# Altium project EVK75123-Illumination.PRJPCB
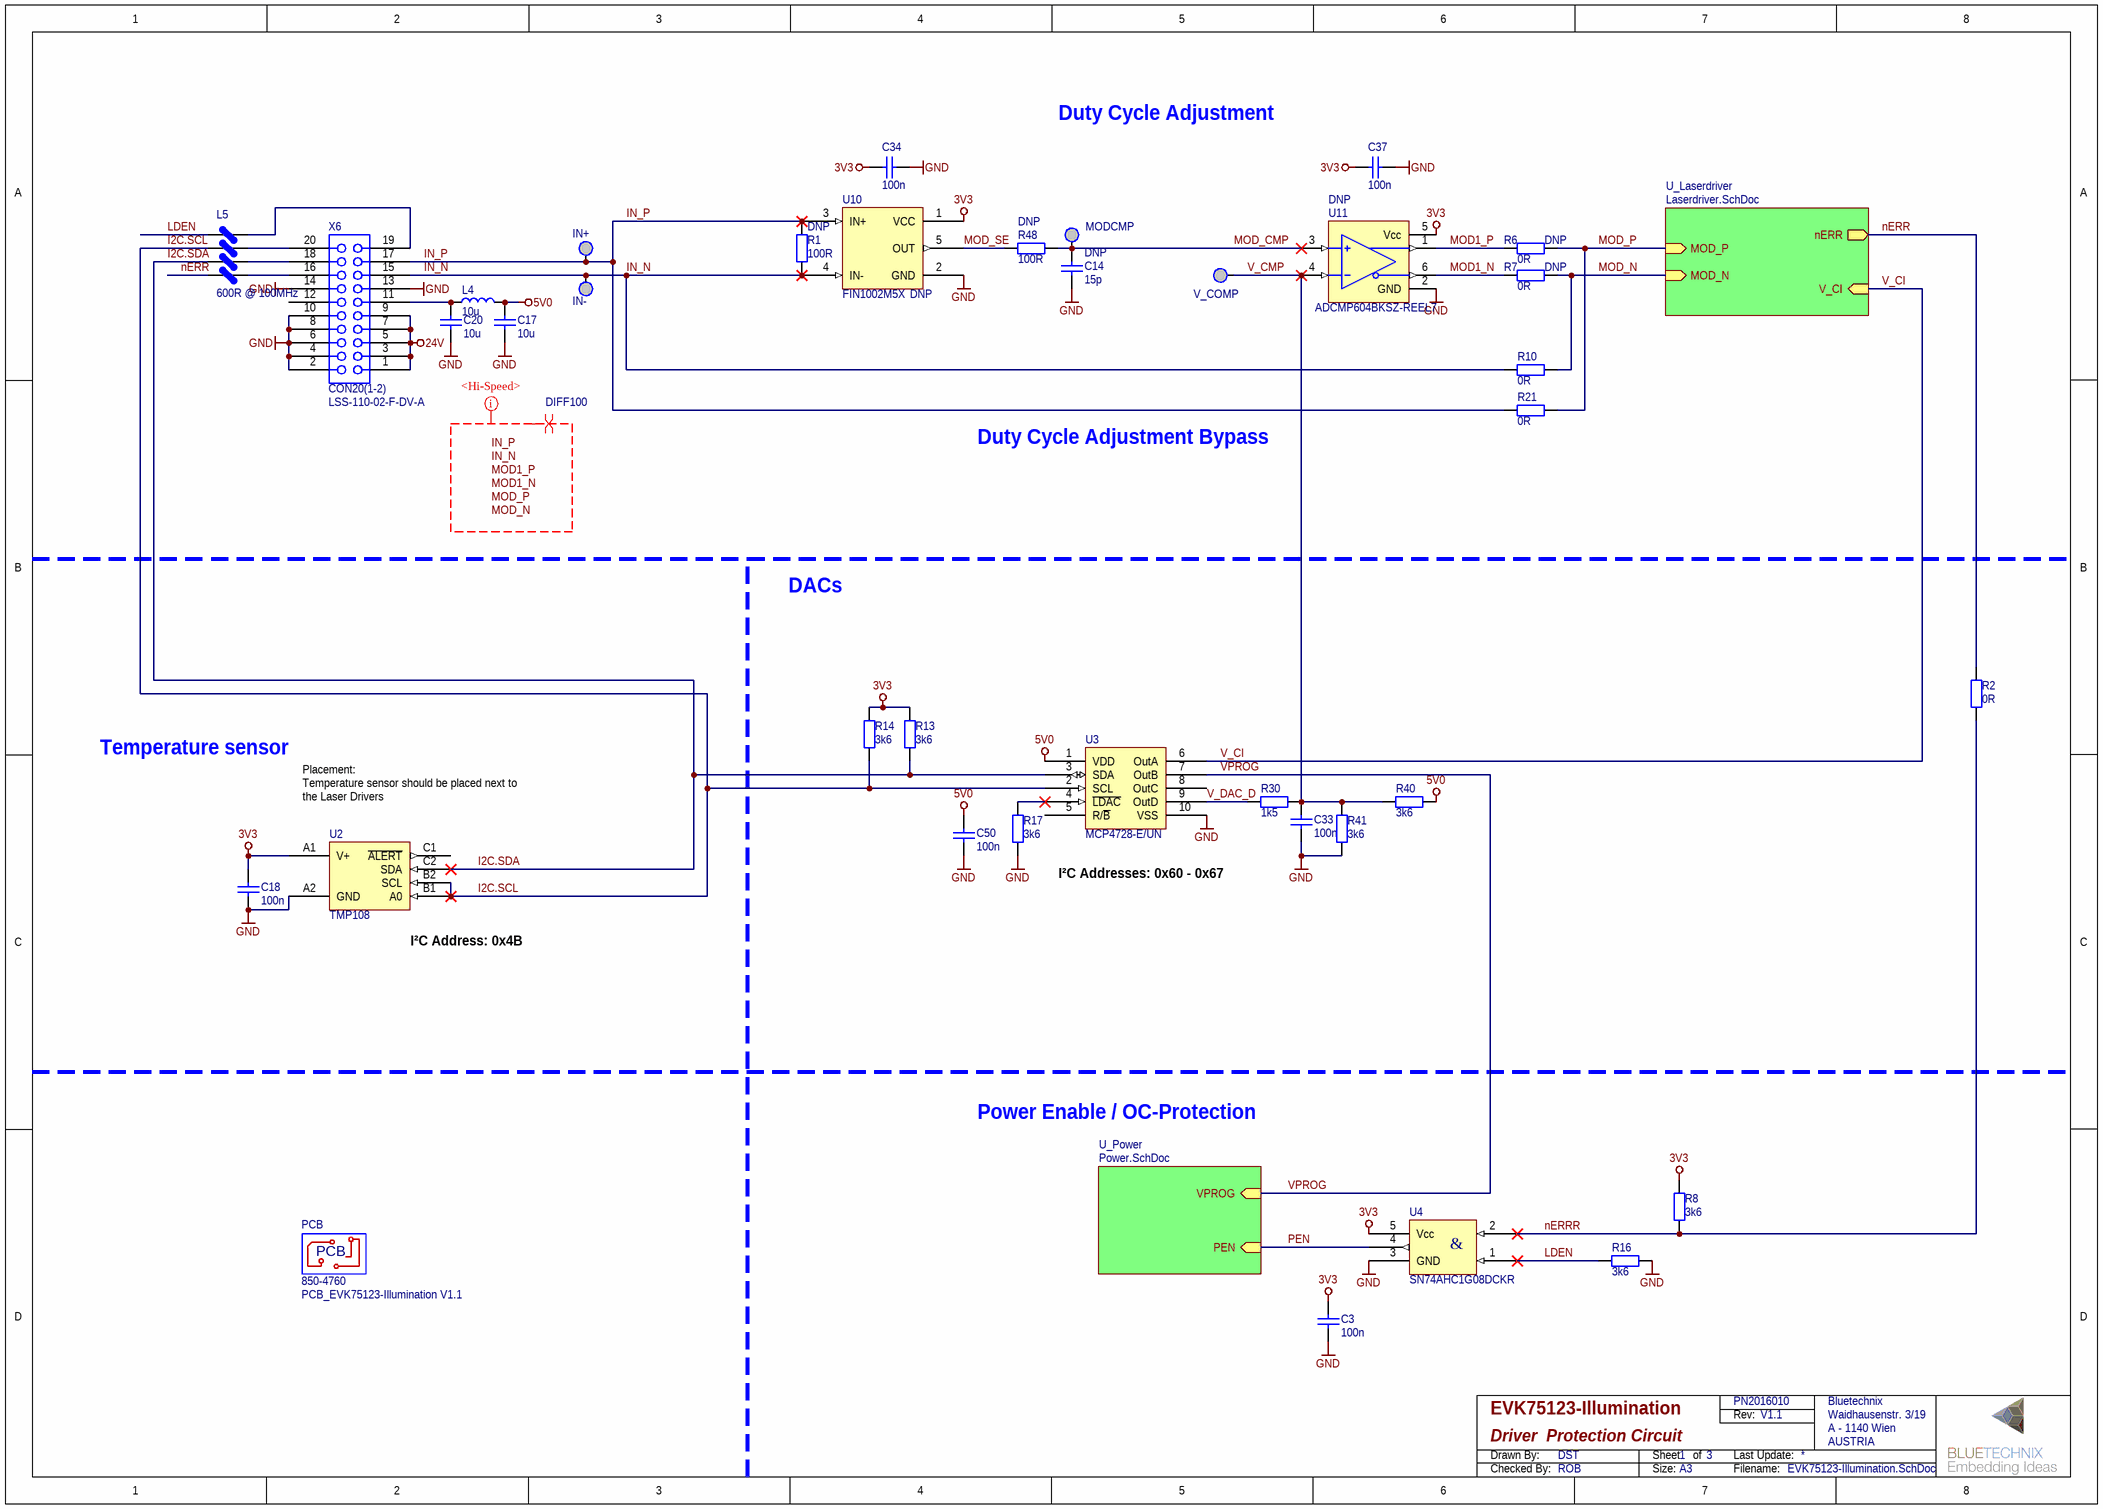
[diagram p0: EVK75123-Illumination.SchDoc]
prj_name: EVK75123-Illumination; prj_num: PN2016010; prj_vers: V1.1
3 sheets, 91 parts. Net scope: hierarchical (ports join the sheet entries above them; power ports are global).
Board file: EVK75123-Illumination.PcbDoc
Sheets:
  EVK75123-Illumination.SchDoc
    U_Power = Power.SchDoc
    U_Laserdriver = Laserdriver.SchDoc

## Sheet EVK75123-Illumination.SchDoc: Driver  Protection Circuit
size A3; CheckedBy: ROB; Author: Vorname Nachname; DrawnBy: DST; Organization: Bluetechnix; Address1: Waidhausenstr. 3/19; Address2: A - 1140 Wien; Address3: AUSTRIA; DocumentNumber: 1; Revision: V1.0; SheetNumber: 1; SheetTotal: 3

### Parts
C3  C: 100n  [0402]  (hidden comment: Capacitor non-polarized)
C14  C: 15p  MountOption: DNP  [0402]  (hidden comment: Capacitor non-polarized)
C17  C: 10u  [0805]  (hidden comment: Capacitor non-polarized)
C18  C: 100n  [0402]  (hidden comment: Capacitor non-polarized)
C20  C: 10u  [0805]  (hidden comment: Capacitor non-polarized)
C33  C: 100n  [0402]  (hidden comment: Capacitor non-polarized)
C34  C: 100n  [0402]  (hidden comment: Capacitor non-polarized)
C37  C: 100n  [0402]  (hidden comment: Capacitor non-polarized)
C50  C: 100n  [0402]  (hidden comment: Capacitor non-polarized)
IN+  Test Pad  [PAD_1mm_SMD]  (value not drawn)  (no BOM)
IN-  Test Pad  [PAD_1mm_SMD]  (value not drawn)  (no BOM)
L4  L: 10u  [1210]  (hidden comment: Inductor)
L5  Z: 600R @ 100MHz  [1206_FB-array]  (hidden comment: Ferrite)
MODCMP  Test Pad  [PAD_1mm_SMD]  (value not drawn)  (no BOM)
PCB  850-4760  [PCB]
R1  R: 100R  MountOption: DNP  [0402]  (hidden comment: Resistor)
R2  R: 0R  [0805]  (hidden comment: Resistor)
R6  R: 0R  MountOption: DNP  [0805]  (hidden comment: Resistor)
R7  R: 0R  MountOption: DNP  [0805]  (hidden comment: Resistor)
R8  R: 3k6  [0402]  (hidden comment: Resistor)
R10  R: 0R  [0805]  (hidden comment: Resistor)
R13  R: 3k6  [0402]  (hidden comment: Resistor)
R14  R: 3k6  [0402]  (hidden comment: Resistor)
R16  R: 3k6  [0402]  (hidden comment: Resistor)
R17  R: 3k6  [0402]  (hidden comment: Resistor)
R21  R: 0R  [0805]  (hidden comment: Resistor)
R30  R: 1k5  [0402]  (hidden comment: Resistor)
R40  R: 3k6  [0402]  (hidden comment: Resistor)
R41  R: 3k6  [0402]  (hidden comment: Resistor)
R48  R: 100R  MountOption: DNP  [0402]  (hidden comment: Resistor)
U2  TMP108  [BGA6-0.4-0.25-1.2x0.8]
U3  NAME: MCP4728-E/UN  [MSOP10-0.5-5]  (hidden comment: MCP4728)
U4  NAME: SN74AHC1G08DCKR  [SOT353-0.65--2.6]  (hidden comment: Single-Gate Dual-Input AND-Logic-Gate)
U10  NAME: FIN1002M5X  MountOption: DNP  [SOT23-5-0.95--3.6]  (hidden comment: FIN1002)
U11  NAME: ADCMP604BKSZ-REEL7  MountOption: DNP  [SOT363-0.65--2.6]  (hidden comment: ADCMP604)
V_COMP  Test Pad  [PAD_1mm_SMD]  (value not drawn)  (no BOM)
X6  CON20(1-2)  NAME: LSS-110-02-F-DV-A  [SAM-LSS-110-02-F-DV-A]

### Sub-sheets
U_Laserdriver = Laserdriver.SchDoc: MOD_P (in), MOD_N (in), nERR (out), V_CI (in)
U_Power = Power.SchDoc: PEN (in), VPROG (in)

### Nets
3V3: C3.1 C18.2 C34.1 C37.1 R8.2 R13.2 R14.2 U2.A1(V+) U4.5(Vcc) U10.1(VCC) U11.5(Vcc)
5V0: C17.2 C50.2 L4.2 R40.1 U3.1(VDD)
24V: X6.1 X6.3 X6.5 X6.7 X6.9
GND: C3.2 C14.1 C17.1 C18.1 C20.1 C33.2 C34.2 C37.2 C50.1 R16.2 R17.1 R41.2 U2.A2(GND) U3.10(VSS) U4.3(GND) U10.2(GND) U11.2(GND) X6.2 X6.4 X6.6 X6.8 X6.10 X6.13 X6.14
I2C.SCL: L5.3 R14.1 U2.B1(A0) U2.B2(SCL) U3.2(SCL)
I2C.SDA: L5.2 R13.1 U2.C2(SDA) U3.3(SDA)
IN_N: IN-.1 R1.2 R10.2 U10.4(IN-) X6.15
IN_P: IN+.1 R1.1 R21.2 U10.3(IN+) X6.17
LDEN: L5.4 R16.1 U4.1(inB)
MOD1_N: R7.2 U11.6(~{Q})
MOD1_P: R6.2 U11.1(Q)
MOD_CMP: C14.2 MODCMP.1 R48.2 U11.3(VP)
MOD_N: R7.1 R10.1 ; sheet U_Laserdriver/MOD_N
MOD_P: R6.1 R21.1 ; sheet U_Laserdriver/MOD_P
MOD_SE: R48.1 U10.5(OUT)
nERR: L5.1 R2.1 ; sheet U_Laserdriver/nERR
nERRR: R2.2 R8.1 U4.2(inA)
PEN: U4.4(out) ; sheet U_Power/PEN
V_CI: U3.6(OutA) ; sheet U_Laserdriver/V_CI
V_CMP: C33.1 R30.2 R40.2 R41.1 U11.4(VN) V_COMP.1
V_DAC_D: R30.1 U3.9(OutD)
VPROG: U3.7(OutB) ; sheet U_Power/VPROG
NetC20_2: C20.2 L4.1 X6.11
NetL5_5: L5.5 X6.19
NetL5_6: L5.6 X6.20
NetL5_7: L5.7 X6.18
NetL5_8: L5.8 X6.16
NetR17_2: R17.2 U3.4(~{LDAC})

Not connected (* = marked no-connect by the designer): U2 C1(~{ALERT}); U3 5(R/~{B}) 8(OutC); X6 12

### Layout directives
net class <Hi-Speed>: IN_N, IN_P, MOD1_N, MOD1_P, MOD_N, MOD_P
differential pair; net class DIFF100: IN_N, IN_P, MOD1_N, MOD1_P, MOD_N, MOD_P

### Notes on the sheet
- Duty Cycle Adjustment
- Duty Cycle Adjustment Bypass
- DACs
- Temperature sensor
- Placement:
  Temperature sensor should be placed next to the Laser Drivers
- I²C Addresses: 0x60 - 0x67
- I²C Address: 0x4B
- Power Enable / OC-Protection
- Labels drawn without touching a wire or pin: IN_N, IN_P, MOD1_N, MOD1_P, MOD_N, MOD_P

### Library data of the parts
C3 = 54C877D5-E705-4C14-AD3D-8F4F7B57D597: C-0402-100n-16V-10%; Manufacturer: Murata; ArticleNumber: 710-0138; NAME: GRM155R71C104KA88D; Inventory Storage Name: LBaut; Inventory Storage Section: C3; Sachgruppe: Keramikscheiben; SachgruppeCode: C_KERAMIK; IsReviewed: 1; Dielektrikum: X7R; Montage: SMD; T-bereich: -55°C : +125°C; T_Koeffizient: ± 15%; Toleranz: 10%; U: 16V; InternalPrice: 0,011693; InternalStock: 600684
C14 = 11FE33DF-B8B2-497C-ADE2-798944BCF4BE: C-0402-15p-50V-5%; Manufacturer: PhyComp; ArticleNumber: 710-0115; NAME: CC0402JRNPO9BN150; Inventory Storage Name: LBaut; Inventory Storage Section: C3; Sachgruppe: C_KERAMIK; SachgruppeCode: Keramikscheiben; IsReviewed: 1; InternalPrice: 0,009; InternalStock: 288; U: 50V; Toleranz: 5%; Dielektrikum: C0G; T_Koeffizient: ± 15%; T-bereich: -55°C : +125°C; Montage: SMD
C17 C20 = 47BE2105-E645-4B7D-88B5-189FA600BE5F: C-0805-10u-10V-10%; Manufacturer: PhyComp; ArticleNumber: 710-0019; NAME: CC0805KKX5R6BB106; Inventory Storage Name: LBaut; Inventory Storage Section: C1; Sachgruppe: C_KERAMIK; SachgruppeCode: Keramikscheiben; IsReviewed: 1; InternalPrice: 0,285138; InternalStock: 500; U: 10V; Toleranz: 10%; Dielektrikum: X5R; T_Koeffizient: ± 15%; T-bereich: -55°C : +85°C; Montage: SMD
C18 = 54C877D5-E705-4C14-AD3D-8F4F7B57D597: C-0402-100n-16V-10%; Manufacturer: Murata; ArticleNumber: 710-0138; NAME: GRM155R71C104KA88D; Inventory Storage Name: LBaut; Inventory Storage Section: C3; Sachgruppe: Keramikscheiben; SachgruppeCode: C_KERAMIK; IsReviewed: 1; U: 16V; Toleranz: 10%; Dielektrikum: X7R; T_Koeffizient: ± 15%; T-bereich: -55°C : +125°C; Montage: SMD; InternalPrice: 0,013001; InternalStock: 607228
C33 C34 C37 C50 = 54C877D5-E705-4C14-AD3D-8F4F7B57D597: C-0402-100n-16V-10%; Manufacturer: Murata; ArticleNumber: 710-0138; NAME: GRM155R71C104KA88D; Inventory Storage Name: LBaut; Inventory Storage Section: C3; Sachgruppe: Keramikscheiben; SachgruppeCode: C_KERAMIK; IsReviewed: 1; Dielektrikum: X7R; Montage: SMD; T-bereich: -55°C : +125°C; T_Koeffizient: ± 15%; Toleranz: 10%; U: 16V; InternalPrice: 0,013001; InternalStock: 607228
IN+ IN- = D58E77CC-74E0-4972-9B60-0D1F1EE06ED8: Test Pad 1mm; Manufacturer: Bluetechnix; ArticleNumber: 810-0021; Inventory Storage Name: L2; SachgruppeCode: SV_TEST; IsReviewed: 1; InternalPrice: 0; Montage: THD
L4 = 5A39A3C7-8FFF-4AB6-80A4-55595FBEE935: L-1210-10u-450mA; Manufacturer: Murata; ArticleNumber: 770-0040; NAME: LQH32CN100K33L; Inventory Storage Name: LBaut; Inventory Storage Section: I4; Sachgruppe: IN_SPEICHERDROSSELN; SachgruppeCode: Speicherdrosseln; IsReviewed: 1; InternalPrice: 0,28; InternalStock: 400; Core: Ferrit; I: 0.45A; Toleranz: 10%; R_dc: 0R3; Q: 35; f_res: 26MHz; Schirm: n; Montage: SMD; T-bereich: -25°C : +85°C
L5 = 17bc767e-4081-41c9-96a1-8705f6a55660: F-1206array-600Z-100mA; Manufacturer: Taiyo Yuden; ArticleNumber: 740-0005; NAME: BK32164M601-T; Inventory Storage Name: LBaut; Inventory Storage Section: L1; Sachgruppe: FI_FERRITPERLEN; SachgruppeCode: Ferritperlen; IsReviewed: 1; InternalPrice: 0,09; InternalStock: 188; Wege: 4; R_dc: 0R6; Bandbreite: 250R @ 1GHz; Frequenz: 220MHz; I_max: 100mA; Bauform: 1206-array; Montage: SMD; T-bereich: -55°C : +125°C
MODCMP V_COMP = 291B522A-DD06-443D-9DB9-AAD5D6CD8DE2: PAD 1x2.54; Manufacturer: Harwin; ArticleNumber: 810-0286; NAME: S2B-ZR; Inventory Storage Name: L2; Inventory Storage Section: Kasten79; Inventory Storage Info: 11063; SachgruppeCode: SV_TEST; IsReviewed: 1; InternalPrice: 0,008; InternalStock: 60; Typ: Crimp; Pole: 2; Gender: m; Winkel: 180°; I_max: 1A; Farbe: naturweiß; Montage: THD
PCB = b0395311-27a9-4c03-a85f-d7f544fec484: PCB_EVK75123-Illumination V1.1; Manufacturer: Bluetechnix; Inventory Storage Name: L2; Sachgruppe: PCB_EXTPROJEKT; SachgruppeCode: externe Projekte; IsReviewed: 0; Kunde: Melexis
R1 R48 = 5753A1E5-EBD2-4BBF-8026-C9AE8047C4EC: R-0402-100R-1%; Manufacturer: YAGEO; ArticleNumber: 780-0309; NAME: RC0402FR-07100RL; Inventory Storage Name: LBaut; Inventory Storage Section: R7; Sachgruppe: Dickschicht; SachgruppeCode: R_DICKSCHICHT; IsReviewed: 1; InternalPrice: 0,041102; InternalStock: 2008; P: 0.063W; Toleranz: 1%; T_Koeffizient: ± 250ppm/°C; Montage: SMD; T-bereich: -55°C : +155°C
R2 R6 R7 R10 R21 = 96878DCE-2E24-48BD-A958-A9B2669E8EA5: R-0805-0R-5%; Manufacturer: YAGEO; ArticleNumber: 780-0259; NAME: RC0805JR-070RL; Inventory Storage Name: LBaut; Inventory Storage Section: R6; Sachgruppe: R_DICKSCHICHT; SachgruppeCode: Dickschicht; IsReviewed: 1; InternalPrice: 0,002857; InternalStock: 9206; P: 0.125W; Toleranz: 5%; T_Koeffizient: ± 250ppm/°C; Montage: SMD
R8 R13 R14 R16 R17 R40 R41 = 87ff11f6-a19c-4fd3-a86d-d729e9959c04: R-0402-3k6-1%; Manufacturer: MULTICOMP; ArticleNumber: 780-0477; NAME: MC 0.0625W 0402 1% 3K6; Inventory Storage Name: LBaut; Sachgruppe: Dickschicht; SachgruppeCode: R_DICKSCHICHT; IsReviewed: 1; InternalPrice: 0,040357; InternalStock: 256; P: 0.0625W; Toleranz: 1%; T_Koeffizient: ± 100ppm/°C; Montage: SMD; T-bereich: -55°C : +155°C; Inventory Storage Section: R10
R30 = 301741e4-a97d-4c83-8d7a-1b789196cb5a: R-0402-1k5-1%; Manufacturer: VISHAY; ArticleNumber: 780-0474; NAME: CRCW04021K50FKED; Inventory Storage Name: LBaut; Inventory Storage Section: R10; Sachgruppe: Dickschicht; SachgruppeCode: R_DICKSCHICHT; IsReviewed: 1; InternalPrice: 0.002142; InternalStock: 8408; P: 63mW; Toleranz: ± 1%; T_Koeffizient: ± 100ppm/°C; Montage: SMD; T-bereich: -55°C bis +155°C
U2 = 1756c951-2cf8-4c64-a988-e546f59afa21: ±1°C Accurate 12bit Digital Temperature Sensor; Manufacturer: Texas Instruments; ArticleNumber: 730-0256; Inventory Storage Name: L2; Sachgruppe: SENSOREN; IsReviewed: 0; Interface: SMBus/I2C; Messbereich: -40°C : +125°C; U: 1.4V : 3.6V; Bauform: WCSP6 (DSBGA-6); Montage: SMD; Kommentar: I²C: 0x70; PM: TA
U3 = 7021478d-2d84-431d-b8be-32d6dfcf2c4d: 12-Bit Digital-to-Analog Converter with EEPROM Memory; Manufacturer: Microchip; ArticleNumber: 700-1100; Inventory Storage Name: L2; Sachgruppe: IC_DATEN_SIGNALWANDLER; SachgruppeCode: Daten-/Signalwandler; IsReviewed: 0; Typ: DAC; Outputs: 4; Interface: I²C; U_IO: 2.7V : 5.5V; Aufloesung: 12bit; f_abtast: 166kHz; T-bereich: -40°C : +125°C; Bauform: MSOP10; Montage: SMD; topmark: 4728UN
U4 = B349E2D1-8349-4508-822A-E73FFBEB3634: 74AHC1G08; Manufacturer: Texas Instruments; ArticleNumber: 700-0623; Inventory Storage Name: LBaut; Inventory Storage Section: U20; Sachgruppe: Logic; SachgruppeCode: IC_LOGIC; IsReviewed: 1; InternalPrice: 0,06506; InternalStock: 172; Logik-Gruppe (NOR): AND; Logik-Typ (7402): 7408; Serie (HCT): AHC; Inputs: 2; Trigger: state; Out-Typ: TTL; t_t: 7ns; U: 2.0V : 5.5V; T-bereich: -40°C : +85°C; Bauform: SOT353-5; Montage: SMD; topmark: AE_
U10 = b52cc92d-fdf7-47cb-bf43-294665300321: LVDS differential line driver; Manufacturer: Fairchild; ArticleNumber: 700-0904; Inventory Storage Name: LBaut; Inventory Storage Section: U36; Sachgruppe: Treiber & Interface; SachgruppeCode: IC_TREIBER_INTERFACE; IsReviewed: 1; InternalPrice: 0,630166; InternalStock: 110; Typ: LVDS receiver; T-bereich: -40°C : +85°C; Bauform: SOT23-5; Montage: SMD; Kommentar: pd: 1.5ns; U: 3V : 3.6V
U11 = cead70f7-3ca7-495c-bd07-28229ce7803b: Rail-to-Rail, Very Fast, 2.5 V to 5.5 V, Single-Supply LVDS Comparator; Manufacturer: Analog Devices; ArticleNumber: 700-1052; Inventory Storage Name: L2; Sachgruppe: Verstärker & Komparatoren; SachgruppeCode: IC_VERSTAERKER_KOMPARATOR; IsReviewed: 0; Anzahl: 1; CMRR: 50dB; U_off: 5mV; P: 37mW; U: 2.5V : 5.5V; T-bereich: -40°C : +125°C; Bauform: SC70; Montage: SMD; topmark: G0Q
X6 = 379f8e5c-a288-4eeb-8f71-ca0e0501eadd: High speed hermaphrodotoc strip; Manufacturer: Samtec; ArticleNumber: 810-0543; Inventory Storage Name: LBaut; Inventory Storage Section: X23; Sachgruppe: Mezzanin; SachgruppeCode: SV_MEZZANIN; IsReviewed: 1; InternalPrice: 0,853333; InternalStock: 60; Typ: B2B; Pole: 20; Gender: h; Winkel: 180°; Reihen: 2; Pitch: 0.635mm; I_max: 1.7A; Montage: SMD; Kommentar: hermaphroditic 7.49mm; T-bereich: -55°C : +125°C

## Sheet Power.SchDoc: Power Supply
size A4; CheckedBy: ROB; Author: Vorname Nachname; DrawnBy: DST; Organization: Bluetechnix; Address1: Waidhausenstr. 3/19; Address2: A - 1140 Wien; Address3: AUSTRIA; DocumentNumber: 3; Revision: V1.0; SheetNumber: 3; SheetTotal: 3
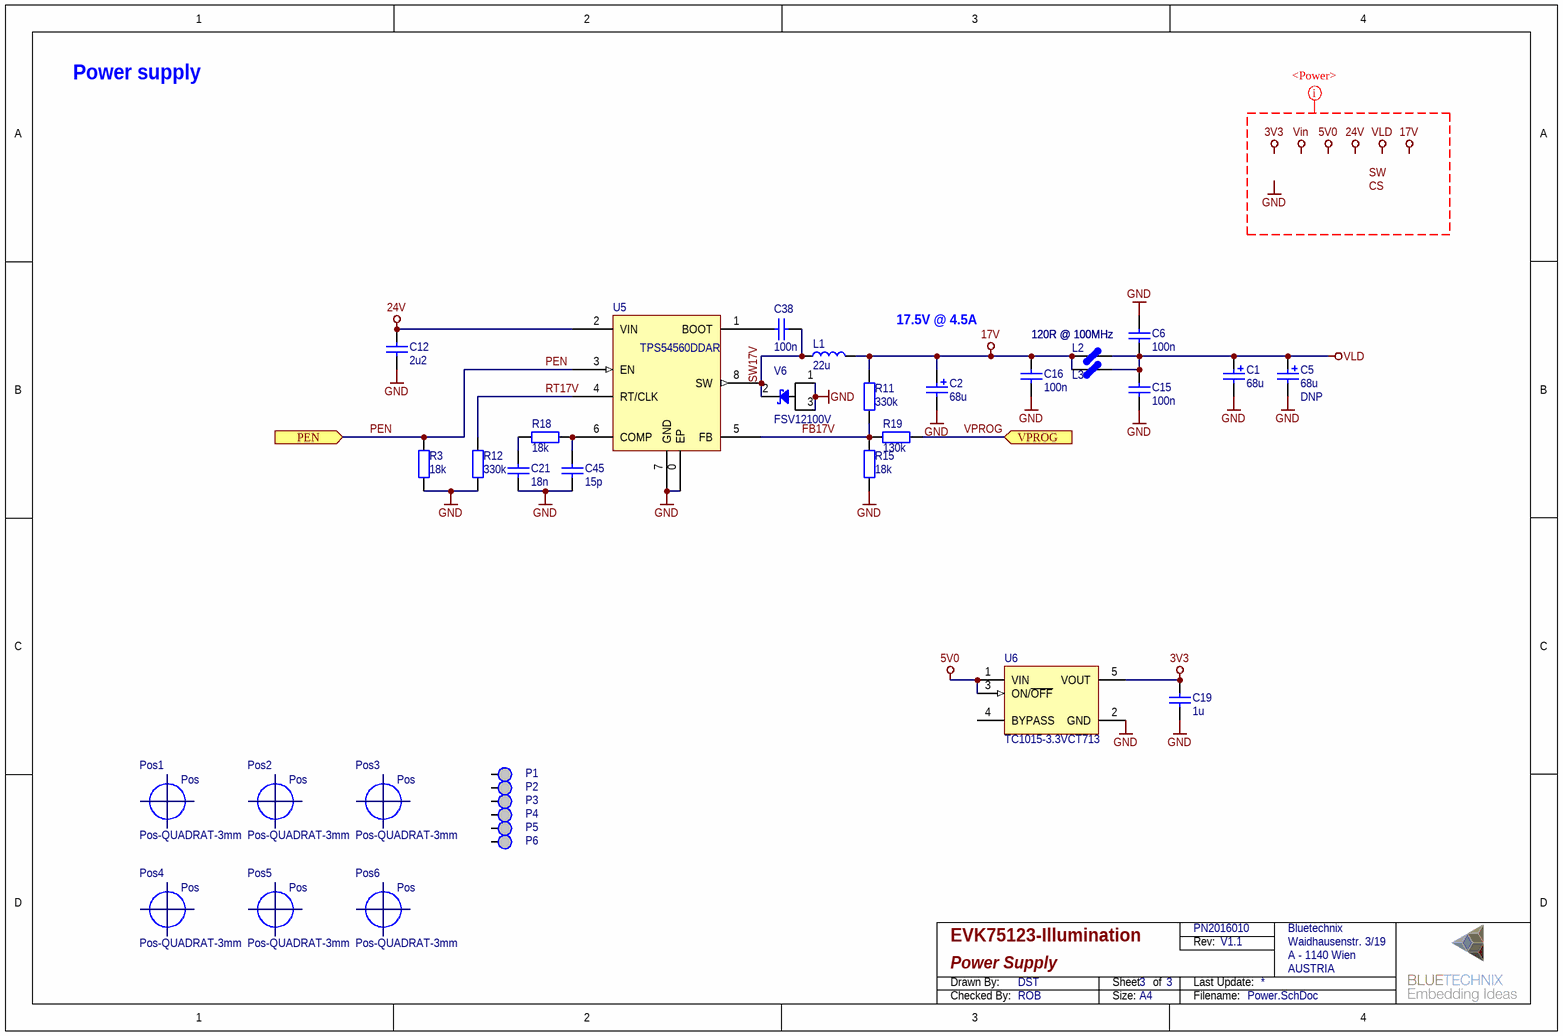
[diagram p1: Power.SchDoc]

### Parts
C1  C: 68u  [ELKO_SMD-8x7]  (hidden comment: Polarized Capicator)
C2  C: 68u  [ELKO_SMD-8x7]  (hidden comment: Polarized Capicator)
C5  C: 68u  MountOption: DNP  [ELKO_SMD-8x7]  (hidden comment: Polarized Capicator)
C6  C: 100n  [1206]  (hidden comment: Capacitor non-polarized)
C12  C: 2u2  [1210]  (hidden comment: Capacitor non-polarized)
C15  C: 100n  [1206]  (hidden comment: Capacitor non-polarized)
C16  C: 100n  [0603]  (hidden comment: Capacitor non-polarized)
C19  C: 1u  [0603]  (hidden comment: Capacitor non-polarized)
C21  C: 18n  [0402]  (hidden comment: Capacitor non-polarized)
C38  C: 100n  [0603]  (hidden comment: Capacitor non-polarized)
C45  C: 15p  [0402]  (hidden comment: Capacitor non-polarized)
L1  L: 22u  [VIS-IHLP-6767DZ]  (hidden comment: Inductor)
L2  Z: 120R @ 100MHz  [0805]  (hidden comment: Ferrite)
L3  Z: 120R @ 100MHz  [0805]  (hidden comment: Ferrite)
P1  Test Pad  [PAD_M2-5x5]  (value not drawn)  (no BOM)
P2  Test Pad  [PAD_M2-5x5]  (value not drawn)  (no BOM)
P3  Test Pad  [PAD_M2-5x5]  (value not drawn)  (no BOM)
P4  Test Pad  [PAD_M2-5x5]  (value not drawn)  (no BOM)
P5  Test Pad  [PAD_M2-5x5]  (value not drawn)  (no BOM)
P6  Test Pad  [PAD_M2-5x5]  (value not drawn)  (no BOM)
Pos1  Position  [Pos-QUADRAT]  (value not drawn)
Pos2  Position  [Pos-QUADRAT]  (value not drawn)
Pos3  Position  [Pos-QUADRAT]  (value not drawn)
Pos4  Position  [Pos-QUADRAT]  (value not drawn)
Pos5  Position  [Pos-QUADRAT]  (value not drawn)
Pos6  Position  [Pos-QUADRAT]  (value not drawn)
R3  R: 18k  [0402]  (hidden comment: Resistor)
R11  R: 330k  [0402]  (hidden comment: Resistor)
R12  R: 330k  [0402]  (hidden comment: Resistor)
R15  R: 18k  [0402]  (hidden comment: Resistor)
R18  R: 18k  [0402]  (hidden comment: Resistor)
R19  R: 130k  [0402]  (hidden comment: Resistor)
U5  NAME: TPS54560DDAR  [PSO8-1.27-7.3]  (hidden comment: TPS54061)
U6  NAME: TC1015-3.3VCT713  [SOT23-5-0.95--3.6]  (hidden comment: LP2985)
V6  NAME: FSV12100V  [TO-277-3]  (hidden comment: Default Diode)

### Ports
PEN (in), VPROG (in)

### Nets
3V3: C19.2 U6.5(VOUT)
5V0: U6.1(VIN) U6.3(ON/~{OFF})
17V: C2.1 C16.1 L1.2 L2.1 L3.1 R11.1
24V: C12.2 U5.2(VIN)
GND: C1.2 C2.2 C5.2 C6.2 C12.1 C15.1 C16.2 C19.1 C21.1 C45.1 R3.1 R12.2 R15.1 U5.0(EP) U5.7(GND) U6.2(GND) V6.1(A) V6.3(A)
VLD: C1.1 C5.1 C6.1 C15.2 L2.2 L3.2
FB17V: R11.2 R15.2 R19.1 U5.5(FB)
PEN: R3.2 U5.3(EN) ; port PEN
RT17V: R12.1 U5.4(RT/CLK)
SW17V: C38.1 L1.1 U5.8(SW) V6.2(K)
VPROG: R19.2 ; port VPROG
NetC21_2: C21.2 R18.2
NetC38_2: C38.2 U5.1(BOOT)
NetC45_2: C45.2 R18.1 U5.6(COMP)

Not connected (* = marked no-connect by the designer): P1 1; P2 1; P3 1; P4 1; P5 1; P6 1; U6 4(BYPASS)

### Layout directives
net class <Power>: 3V3, 5V0, 17V, 24V, CS, GND, SW, Vin, VLD

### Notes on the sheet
- Power supply
- 17.5V @ 4.5A
- Labels drawn without touching a wire or pin: 3V3, 5V0, 17V, 24V, CS, GND, SW, Vin, VLD

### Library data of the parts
C1 C2 C5 = 15423dca-9b42-4089-8a58-6a30d5d5cf06: C-68u-35V-20%-44mR; Manufacturer: Nichicon; ArticleNumber: 710-0371; NAME: PCR1V680MCL1GS; Inventory Storage Name: L2; Sachgruppe: C_ALUMINIUM_ELKO; SachgruppeCode: Aluminium Elektrolyt; IsReviewed: 1; InternalPrice: 1,13625; InternalStock: 20; U: 35V; Toleranz: 20%; ESR: 44mR; Z: 44mR @ 100kHz; T-bereich: -55°C : +125°C; Lebensdauer: 4000h @ 125°C; Bauform: 8.3x8.3x6.9; Montage: SMD
C6 C15 = 6574bd8d-1f7f-4017-8c13-fc1ff6c564f2: C-1206-100n-50V-5%; Manufacturer: TDK; ArticleNumber: 710-0354; NAME: CGA5L2C0G1H104J160AA; Inventory Storage Name: L2; Sachgruppe: C_KERAMIK; SachgruppeCode: Keramikscheiben; IsReviewed: 1; InternalPrice: 0; InternalStock: 12; U: 50V; Toleranz: 5%; Dielektrikum: C0G; T-bereich: -55°C : +125°C; Montage: SMD
C12 = c11633e3-883f-4ea1-bab5-305a930c1712: C-1210-2u2-100V-X7R; Manufacturer: Kemet; ArticleNumber: 710-0311; NAME: C1210C225K1RACTU; Inventory Storage Name: LBaut; Inventory Storage Section: C6; Sachgruppe: C_KERAMIK; SachgruppeCode: Keramikscheiben; IsReviewed: 1; InternalPrice: 0,24625; InternalStock: 20; U: 100V; Toleranz: 10%; Dielektrikum: X7R; T_Koeffizient: ± 15%; T-bereich: -55°C : +125°C; Montage: SMD
C16 C38 = F4F417EB-80BB-43BD-9294-E69FEC10CC02: C-0603-100n-50V-10%; Manufacturer: MULTICOMP; ArticleNumber: 710-0283; NAME: MCCA000255; Inventory Storage Name: LBaut; Inventory Storage Section: C6; Sachgruppe: Keramikscheiben; SachgruppeCode: C_KERAMIK; IsReviewed: 1; InternalPrice: 0,01; InternalStock: 1912; U: 50V; Toleranz: 10%; Dielektrikum: X7R; T_Koeffizient: ± 15%; T-bereich: -55°C : +125°C; Montage: SMD
C19 = 62C539F0-6F12-4C64-8973-B77ABBA35E0D: C-0603-1u-25V-10%; Manufacturer: Kemet; ArticleNumber: 710-0184; NAME: C0603C105K3PACTU; Inventory Storage Name: LBaut; Inventory Storage Section: C4; Sachgruppe: C_KERAMIK; SachgruppeCode: Keramikscheiben; IsReviewed: 1; InternalPrice: 0,009729; InternalStock: 756; U: 25V; Toleranz: 10%; Dielektrikum: X5R; T_Koeffizient: ± 15%; T-bereich: -55°C : +85°C; Montage: SMD
C21 = 0D03DA8E-6E9D-48FA-B2D5-DDC88D2A4CF2: C-0402-18n-16V-10%; Manufacturer: AVX; ArticleNumber: 710-0219; NAME: 0402YC183KAT2A; Inventory Storage Name: LBaut; Inventory Storage Section: C5; Sachgruppe: C_KERAMIK; SachgruppeCode: Keramikscheiben; IsReviewed: 1; InternalPrice: 0; U: 16V; Toleranz: 10%; Dielektrikum: X7R; T_Koeffizient: ±15%; T-bereich: -55°C : +125°C; Montage: SMD
C45 = 11FE33DF-B8B2-497C-ADE2-798944BCF4BE: as C14 on sheet EVK75123-Illumination
L1 = c927bdf3-e195-4335-ae34-2dcccbc64859: L-VIS-IHLP-6767-22u-6.2A-20%; Manufacturer: Vishay; ArticleNumber: 770-0190; NAME: IHLP6767DZER220M11; Inventory Storage Name: L2; Sachgruppe: IN_SPEICHERDROSSELN; SachgruppeCode: Speicherdrosseln; IsReviewed: 0; I: 7.2A; I_sat: 6.2A; Toleranz: 20%; R_dc: 0R043; f_res: 5MHz; Schirm: y; Bauform: 17 x 17 x 4 mm; Montage: SMD; T-bereich: -55°C : +155°C
L2 L3 = 4558f3ef-a2ca-4732-a97e-33e36c5aad12: F-0805-120Z-5A; Manufacturer: MEC MARCOM; ArticleNumber: 740-0008; NAME: MLB-201209-0120PU; Inventory Storage Name: LBaut; Inventory Storage Section: L2; Sachgruppe: FI_FERRITPERLEN; SachgruppeCode: Ferritperlen; IsReviewed: 1; InternalPrice: 0,068522; InternalStock: 84; R_dc: 0R02; Bandbreite: 110R @ 1GHz; Frequenz: 300MHz; I_max: 5A; Montage: SMD; T-bereich: -55°C : +125°C
P1-P6 = d95d2f47-965b-47b2-ac00-e8d5b9325de3: M2 Mounting Hole 5x5; Manufacturer: Bluetechnix; ArticleNumber: 810-0545; Inventory Storage Name: L2; SachgruppeCode: SV_TEST; IsReviewed: 1; InternalPrice: 0; Typ: Mount Hole
Pos1-Pos6 = A97550DC-E5EA-465D-9168-34E3565B8720: Pos-QUADRAT-3mm; Manufacturer: Bluetechnix; MountOption: DNP; ArticleNumber: 880-0007; Inventory Storage Name: L2; Sachgruppe: PCB-Symbole; SachgruppeCode: DIV_SYMBOLE; IsReviewed: 1; Groesse: 3mm; InternalPrice: 0
R3 R15 = A4A7BB00-465D-4C1E-8319-4836672F5686: R-0402-18k-1%; Manufacturer: YAGEO; ArticleNumber: 780-0108; NAME: RC0402FR-0718KL; Inventory Storage Name: LBaut; Inventory Storage Section: R3; Sachgruppe: R_DICKSCHICHT; SachgruppeCode: Dickschicht; IsReviewed: 1; InternalPrice: 0,009565; InternalStock: 808; P: 0.063W; Toleranz: 1%; T_Koeffizient: ± 250ppm/°C; Montage: SMD; T-bereich: -55°C : +155°C
R11 R12 = 0499915E-9BF4-4C7F-8B08-D182950F3B89: R-0402-330k-1%; Manufacturer: YAGEO; ArticleNumber: 780-0326; NAME: RC0402FR-07330KL; Inventory Storage Name: LBaut; Inventory Storage Section: R7; Sachgruppe: R_DICKSCHICHT; SachgruppeCode: Dickschicht; IsReviewed: 1; InternalPrice: 0,01625; InternalStock: 86; P: 0.063W; Toleranz: 1%; T_Koeffizient: ± 250ppm/°C; Montage: SMD; T-bereich: -55°C : +155°C
R18 = A4A7BB00-465D-4C1E-8319-4836672F5686: R-0402-18k-1%; Manufacturer: YAGEO; ArticleNumber: 780-0108; NAME: RC0402FR-0718KL; Inventory Storage Name: LBaut; Inventory Storage Section: R3; Sachgruppe: R_DICKSCHICHT; SachgruppeCode: Dickschicht; IsReviewed: 1; InternalPrice: 0,00923; InternalStock: 972; P: 0.063W; Toleranz: 1%; T_Koeffizient: ± 250ppm/°C; Montage: SMD; T-bereich: -55°C : +155°C
R19 = 57b0607b-283e-4831-8b97-1b038861c010: R-0402-130k-1%; Manufacturer: Multcomp; ArticleNumber: 780-0509; NAME: MCMR04X1303FTL; Inventory Storage Name: LBaut; Inventory Storage Section: R11; Sachgruppe: R_DICKSCHICHT; SachgruppeCode: Dickschicht; IsReviewed: 1; InternalPrice: 0,001481; InternalStock: 122; P: 0.063W; Toleranz: 1%; T_Koeffizient: ± 100ppm/°C; Montage: SMD; T-bereich: -55°C : +125°C
U5 = 83e8cd34-1e26-4937-9357-3a852f02699a: 4.5 V to 60 V Input, 5 A, Step Down DC-DC Converter with Eco-mode; Manufacturer: Texas Instruments; ArticleNumber: 700-1098; Inventory Storage Name: LBaut; Inventory Storage Section: U48; Sachgruppe: PM_BUCK; SachgruppeCode: Buck; IsReviewed: 0; InternalPrice: 2,225; InternalStock: 2; U_in(max): 60V; U_in(min): 4.5V; U_out(max): 58.8V; U_out(min): 0.8V; fix_var: var; I_out: 5A; T-bereich: -40°C : +150°C; Bauform: HSOP8; Montage: SMD; Frequenz: 100kHz : 2.5MHz
U6 = 595174d6-4f0f-4a85-858e-941119242838: 3.3V, Micropower 100 mA Low-Noise Ultra Low-Dropout Regulator; Manufacturer: Microchip Technology; ArticleNumber: 700-0834; Inventory Storage Name: LBaut; Inventory Storage Section: U31; Sachgruppe: PM_LINEAR; SachgruppeCode: Linear; IsReviewed: 1; InternalPrice: 0,255; InternalStock: 136; Typ: 3V3 LDO; U_in(max): 6V; U_in(min): 2.7V; fix_var: fix; I_out: 100mA; U_drop_out: 180mV; T-bereich: -40°C : +125°C; Bauform: SOT235; Montage: SMD; topmark: TC1015
V6 = a2494603-b754-4332-b2d6-676b3f1482f6: 12A, 100V Ultra-Low Vf Schottky Rectifier; Manufacturer: Fairchild; ArticleNumber: 730-0269; Inventory Storage Name: LBaut; Sachgruppe: SE_SCHOTTKY; IsReviewed: 1; U_f: 483mV @ 5A, 25°C; I_f(max): 220A; I_r: 22.5uA; t_rr: 27.33ns; C_@_U_r_f: 1124pF @ 4V, 1MHz; Montage: SMD; T-bereich: -55°C : +150°C; InternalPrice: 0,18; InternalStock: 22; Inventory Storage Section: V19

## Sheet Laserdriver.SchDoc: Driver  Protection Circuit
size A4; CheckedBy: ROB; Author: Vorname Nachname; DrawnBy: DST; Organization: Bluetechnix; Address1: Waidhausenstr. 3/19; Address2: A - 1140 Wien; Address3: AUSTRIA; DocumentNumber: 2; Revision: V1.0; SheetNumber: 2; SheetTotal: 3
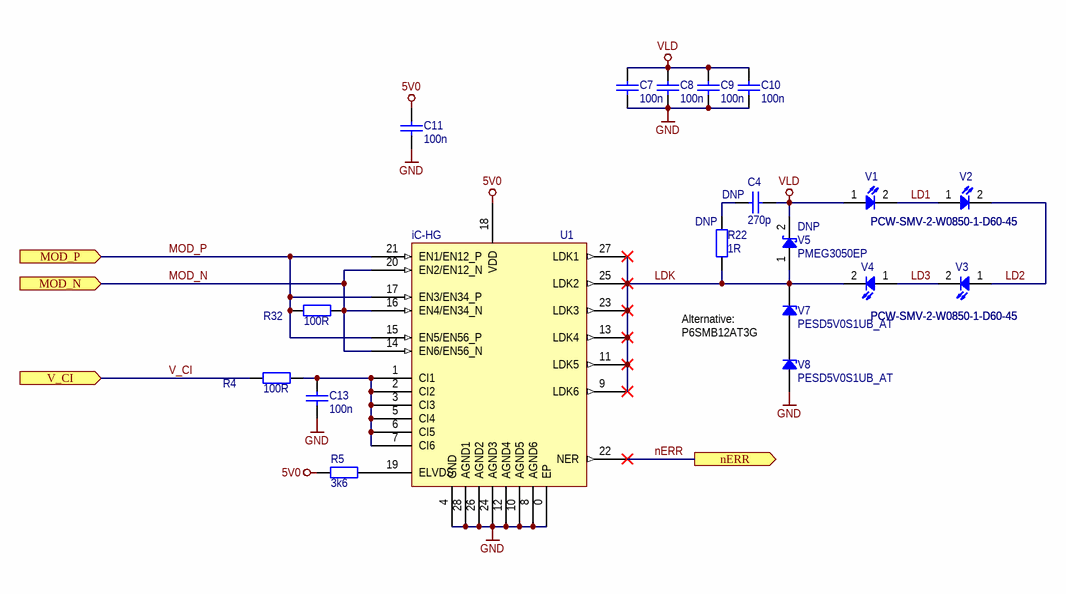
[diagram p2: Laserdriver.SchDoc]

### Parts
C4  C: 270p  MountOption: DNP  [0402]  (hidden comment: Capacitor non-polarized)
C7  C: 100n  [1206]  (hidden comment: Capacitor non-polarized)
C8  C: 100n  [1206]  (hidden comment: Capacitor non-polarized)
C9  C: 100n  [1206]  (hidden comment: Capacitor non-polarized)
C10  C: 100n  [1206]  (hidden comment: Capacitor non-polarized)
C11  C: 100n  [1206]  (hidden comment: Capacitor non-polarized)
C13  C: 100n  [0402]  (hidden comment: Capacitor non-polarized)
R4  R: 100R  [0402]  (hidden comment: Resistor)
R5  R: 3k6  [0402]  (hidden comment: Resistor)
R22  R: 1R  MountOption: DNP  [1206]  (hidden comment: Resistor)
R32  R: 100R  [0402]  (hidden comment: Resistor)
U1  iC-HG  [QFN28-0.5-5-0.9]
V1  NAME: PCW-SMV-2-W0850-1-D60-45  [PCW-SMT-2]  (hidden comment: Light Emitting Diode)
V2  NAME: PCW-SMV-2-W0850-1-D60-45  [PCW-SMT-2]  (hidden comment: Light Emitting Diode)
V3  NAME: PCW-SMV-2-W0850-1-D60-45  [PCW-SMT-2]  (hidden comment: Light Emitting Diode)
V4  NAME: PCW-SMV-2-W0850-1-D60-45  [PCW-SMT-2]  (hidden comment: Light Emitting Diode)
V5  MountOption: DNP  [SOD128]  (hidden comment: Schottky Diode)
V7  NAME: PESD5V0S1UB_AT  [SOD523]  (hidden comment: Z-Diode)
V8  NAME: PESD5V0S1UB_AT  [SOD523]  (hidden comment: Z-Diode)

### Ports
MOD_N (in), MOD_P (in), nERR (out), V_CI (in)

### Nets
5V0: C11.2 R5.2 U1.18(VDD)
GND: C7.1 C8.1 C9.1 C10.1 C11.1 C13.1 U1.0(EP) U1.4(GND) U1.8(AGND6) U1.10(AGND5) U1.12(AGND4) U1.24(AGND3) U1.26(AGND2) U1.28(AGND1) V8.1(A)
VLD: C4.2 C7.2 C8.2 C9.2 C10.2 V1.1(A) V5.2(K)
LD1: V1.2(K) V2.1(A)
LD2: V2.2(K) V3.1(A)
LD3: V3.2(K) V4.1(A)
LDK: R22.1 U1.9(LDK6) U1.11(LDK5) U1.13(LDK4) U1.23(LDK3) U1.25(LDK2) U1.27(LDK1) V4.2(K) V5.1(A) V7.2(K)
MOD_N: R32.1 U1.14(EN6/EN56_N) U1.16(EN4/EN34_N) U1.20(EN2/EN12_N) ; port MOD_N
MOD_P: R32.2 U1.15(EN5/EN56_P) U1.17(EN3/EN34_P) U1.21(EN1/EN12_P) ; port MOD_P
nERR: U1.22(NER) ; port nERR
V_CI: R4.2 ; port V_CI
NetC4_1: C4.1 R22.2
NetC13_2: C13.2 R4.1 U1.1(CI1) U1.2(CI2) U1.3(CI3) U1.5(CI4) U1.6(CI5) U1.7(CI6)
NetR5_1: R5.1 U1.19(ELVDS)
NetV7_1: V7.1(A) V8.2(K)

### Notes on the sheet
- Alternative:
  P6SMB12AT3G

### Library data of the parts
C4 = 0097ADC0-227E-4059-A51E-B4508658C31A: C-0402-270p-50V-5%; Manufacturer: KEMET; ArticleNumber: 710-0179; NAME: C0402C271J5GACTU; Inventory Storage Name: LBaut; Inventory Storage Section: C4; Sachgruppe: C_KERAMIK; SachgruppeCode: Keramikscheiben; IsReviewed: 1; InternalPrice: 0; U: 50V; Toleranz: 5%; Dielektrikum: C0G; T_Koeffizient: ± 30ppm/°C; T-bereich: -55°C : +125°C; Montage: SMD
C7-C11 = 6574bd8d-1f7f-4017-8c13-fc1ff6c564f2: as C6 on sheet Power
C13 = 54C877D5-E705-4C14-AD3D-8F4F7B57D597: as C18 on sheet EVK75123-Illumination
R4 R32 = 5753A1E5-EBD2-4BBF-8026-C9AE8047C4EC: as R1 on sheet EVK75123-Illumination
R5 = 87ff11f6-a19c-4fd3-a86d-d729e9959c04: as R8 on sheet EVK75123-Illumination
R22 = 1a6a65a5-8098-42a8-a07d-6c7b13c9a3e6: R-1206-1R-1%-0.5W; Manufacturer: Multicomp; ArticleNumber: 780-0490; NAME: MCHP06W2F100KT5E; Inventory Storage Name: LBaut; Inventory Storage Section: R10; Sachgruppe: R_DICKSCHICHT; SachgruppeCode: Dickschicht; IsReviewed: 1; InternalPrice: 0,021929; InternalStock: 570; P: 0.5W; Toleranz: 1%; T_Koeffizient: ± 200ppm/°C; Montage: SMD; T-bereich: -55°C : 155°C
U1 = 900fa9a9-c7df-41b9-b82b-983ec3f9771c: 3 A LASER SWITCH; Manufacturer: iC-Haus; ArticleNumber: 700-1004; Inventory Storage Name: L2; Sachgruppe: Treiber & Interface; SachgruppeCode: IC_TREIBER_INTERFACE; IsReviewed: 1; InternalPrice: 0; Typ: Laser Diode Driver; Wege: 6; Interface: TTL/LVDS; T-bereich: -40°C : +85°C; Bauform: QFN28; Montage: SMD; U: VDD=3V : 5.5V, VH=12V
V1-V4 = 85e564f8-3a71-4d92-9828-a8b6dfe11ab7: VCSEL Array Laser Diode; Manufacturer: Princeton Optronics; ArticleNumber: 730-0248; Inventory Storage Name: L2; Sachgruppe: SE_LED; IsReviewed: 0; Farbe: IR; Lichtstaerke: 2W CW; Winkel: 60° x 45°; U_f: 2V; I_f(nenn): 2.7A; Lambda: 850nm; I_f(max): 10A; Anzahl: 1; Montage: SMD; T-bereich: 0°C : 80°C
V5 = 39a5ee8a-d88f-425e-8062-ede2c4d3764b: PMEG3050EP; Manufacturer: NXP; ArticleNumber: 730-0176; Inventory Storage Name: LBaut; Inventory Storage Section: V15; Sachgruppe: SE_SCHOTTKY; IsReviewed: 1; InternalPrice: 0,265555; InternalStock: 156; U_f: 0.36V; U_r: 30V; I_f(nenn): 5A; I_f(max): 70A; I_r: 2.6mA; C_@_U_r_f: 260pF @ 10V; Bauform: SOD-128; Montage: SMD; T-bereich: -55°C : +150°C; topmark: A7
V7 V8 = CC9D59A8-5C7A-4322-9DFB-934945E300CD: PESD5V0S1UB - 5.0V; Manufacturer: NXP; ArticleNumber: 730-0062; Inventory Storage Name: LBaut; Inventory Storage Section: V4; Sachgruppe: PC_TVS; SachgruppeCode: TVS; IsReviewed: 1; InternalPrice: 0,2928; InternalStock: 42; Typ: TVS Diode; U_betrieb: 5V; U_brkdn: 6.8V; P: 260W; Montage: SMD; I_pp: 15A; uni_bip: uni; Bauform: SOD-523; T-bereich: -65°C : +150°C

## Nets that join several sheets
3V3: EVK75123-Illumination (11 pins), Power (C19.2 U6.5)
5V0: EVK75123-Illumination (5 pins), Power (U6.1 U6.3), Laserdriver (C11.2 R5.2 U1.18)
24V: EVK75123-Illumination (5 pins), Power (C12.2 U5.2)
GND: EVK75123-Illumination (24 pins), Power (18 pins), Laserdriver (15 pins)
VLD: Power (6 pins), Laserdriver (7 pins)
MOD_N: EVK75123-Illumination (R7.1 R10.1), Laserdriver (R32.1 U1.14 U1.16 U1.20)
MOD_P: EVK75123-Illumination (R6.1 R21.1), Laserdriver (R32.2 U1.15 U1.17 U1.21)
nERR: EVK75123-Illumination (L5.1 R2.1), Laserdriver (U1.22)
PEN: EVK75123-Illumination (U4.4), Power (R3.2 U5.3)
V_CI: EVK75123-Illumination (U3.6), Laserdriver (R4.2)
VPROG: EVK75123-Illumination (U3.7), Power (R19.2)

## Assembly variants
60° x 40°: not fitted V13_L V13_R V14_L V14_R V15_L V15_R V16_L V16_R V17_L V17_R V18_L V18_R V19_L V19_R V20_L V20_R
110°: not fitted V17_L V17_R V18_L V18_R V19_L V19_R V20_L V20_R; alternate parts V1_R -> 27129d98-1344-4fb2-a297-1e36a3f61028, V2_R -> 27129d98-1344-4fb2-a297-1e36a3f61028, V3_R -> 27129d98-1344-4fb2-a297-1e36a3f61028, V4_R -> 27129d98-1344-4fb2-a297-1e36a3f61028, V1_L -> 27129d98-1344-4fb2-a297-1e36a3f61028, V2_L -> 27129d98-1344-4fb2-a297-1e36a3f61028, V3_L -> 27129d98-1344-4fb2-a297-1e36a3f61028, V4_L -> 27129d98-1344-4fb2-a297-1e36a3f61028
19°: not fitted V13_L V13_R V14_L V14_R V15_L V15_R V16_L V16_R; alternate parts V4_L -> e9a740a4-88eb-4583-a0a4-5d5badcb96cd, V3_L -> e9a740a4-88eb-4583-a0a4-5d5badcb96cd, V2_L -> e9a740a4-88eb-4583-a0a4-5d5badcb96cd, V1_L -> e9a740a4-88eb-4583-a0a4-5d5badcb96cd, V4_R -> e9a740a4-88eb-4583-a0a4-5d5badcb96cd, V3_R -> e9a740a4-88eb-4583-a0a4-5d5badcb96cd, V2_R -> e9a740a4-88eb-4583-a0a4-5d5badcb96cd, V1_R -> e9a740a4-88eb-4583-a0a4-5d5badcb96cd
